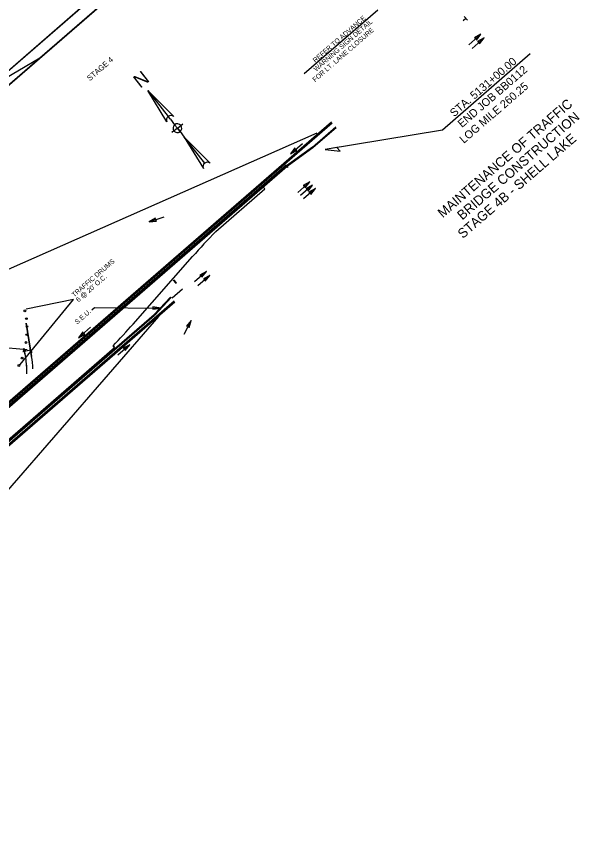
# Model space of a CAD drawing. Extents: x 259983 to 267998, y 211467 to 219827.
# Drawn here: x 266591 to 267998, y 211577 to 213621 of the extents above; entities that cross this region are included whole.
import ezdxf

# ---------------------------------------------------------------- set-up
doc = ezdxf.new("R2010")
doc.units = 0
for name, color, linetype in [('1', 7, 'Continuous'), ('Default', 7, 'Continuous'), ('DRAINAGE', 7, 'Continuous'), ('Level 1', 7, 'Continuous'), ('Level 24', 7, 'Continuous'), ('Level 43', 7, 'Continuous'), ('Level 58', 7, 'Continuous'), ('Level 59', 7, 'Continuous'), ('Level 6', 7, 'Continuous'), ('R_MOT', 7, 'Continuous'), ('R_MOT STAGE 1', 7, 'Continuous'), ('R_MOT STAGE 2', 7, 'Continuous')]:
    doc.layers.add(name, color=color, linetype=linetype)

msp = doc.modelspace()

# ---------------------------------------------------------------- linework, layer by layer
at = {"layer": '1'}
for p, q in [((266779.5, 212887.4), (266786.2, 212893.2)), ((266786.2, 212893.2), (266951.8, 212892.1))]:
    msp.add_line(p, q, dxfattribs=at)
for points in [[(265439.2, 211680.6), (266025.4, 212744.6), (266011.1, 212775.1), (266035.2, 212752.4), (267342.6, 213329.5)], [(265871.3, 211879.9), (266434.6, 212283), (266462.7, 212264.5), (266443.7, 212291.7), (266947.2, 212871.1)]]:
    msp.add_lwpolyline(points, dxfattribs=at)
msp.add_lwpolyline([(266931.9, 212889.3), (266951.8, 212892.1), (266932, 212895.3)], close=True, dxfattribs=at)
at = {"layer": 'Default'}
for p, q in [((266493.8, 213418.3), (267204.5, 214033.5)), ((266947.4, 213811), (266236.7, 213195.7)), ((266511.6, 213397.7), (266965.2, 213790.4)), ((266524.9, 213443.6), (266649.8, 213517.3))]:
    msp.add_line(p, q, dxfattribs=at)
at = {"layer": 'DRAINAGE'}
for p, q in [((266989.8, 212954.2), (266983.2, 212961.7)), ((266990.9, 212955.1), (266984.3, 212962.7)), ((266989.8, 212954.2), (266990.9, 212955.1))]:
    msp.add_line(p, q, dxfattribs=at)
at = {"layer": 'Level 1'}
for p, q in [((266919.6, 213435.8), (266984.5, 213370.5)), ((266967.3, 213357.1), (266919.6, 213435.8)), ((266919.6, 213435.8), (266970.6, 213370.6)), ((266975.9, 213363.8), (266970.6, 213370.6)), ((266975.9, 213363.8), (266986.7, 213350.1)), ((266986.7, 213350.1), (266993.4, 213341.5)), ((266993.4, 213341.5), (267001.9, 213348.2)), ((267001.9, 213348.2), (267007.1, 213352.2)), ((267001.9, 213348.2), (267001.9, 213348.2)), ((266984.5, 213334.5), (266979.6, 213330.8)), ((266993.4, 213341.5), (266985.1, 213335)), ((266993.4, 213341.5), (267000.1, 213332.9)), ((267000.1, 213332.9), (266993.4, 213341.5)), ((267000.1, 213332.9), (267010.8, 213319.2)), ((267010.8, 213319.2), (267058.5, 213240.4)), ((267061.7, 213254), (267010.8, 213319.2)), ((267010.8, 213319.2), (267075.7, 213253.8))]:
    msp.add_line(p, q, dxfattribs=at)
for centre, radius, start, end in [((266977.4, 213361.9), 11.2, 128, 205.3196), ((266977.4, 213361.9), 11.2, 50.6804, 128), ((266993.4, 213341.5), 10.9, 128, 218), ((266993.4, 213341.5), 10.9, 38, 128), ((266993.4, 213341.5), 10.9, 308, 38), ((266993.4, 213341.5), 10.9, 218, 308), ((267068.6, 213245.2), 11.2, 128, 205.3196), ((267068.6, 213245.2), 11.2, 50.6804, 128)]:
    msp.add_arc(centre, radius, start, end, dxfattribs=at)
at = {"layer": 'Level 24'}
for points in [[(267875.2, 213526.9), (267655.6, 213336.8)], [(267655.6, 213336.8), (267363, 213288.5)]]:
    msp.add_lwpolyline(points, dxfattribs=at)
at = {"layer": 'Level 43'}
for points in [[(267751.7, 213576), (267721.7, 213550)], [(267759.6, 213566.8), (267729.6, 213540.9)], [(267275.7, 213277.4), (267305.8, 213303.4)], [(267324.2, 213207.1), (267294.2, 213181.1)], [(267331.3, 213199), (267301.3, 213173)], [(267338.4, 213190.8), (267308.3, 213164.8)], [(266922.6, 213107.4), (266960.3, 213120)], [(267065.9, 212983.5), (267035.9, 212957.6)], [(267074.5, 212973.6), (267044.5, 212947.6)], [(267027.9, 212861.4), (267009.6, 212826.2)], [(266746.1, 212818.1), (266776.1, 212844.1)], [(266874.5, 212800.5), (266844.4, 212774.5)]]:
    msp.add_lwpolyline(points, dxfattribs=at)
at = {"layer": 'Level 58'}
for points in [[(267740.5, 213561.4), (267751.7, 213576), (267735.6, 213567.1), (267740.3, 213566.2)], [(267748.5, 213552.2), (267759.6, 213566.8), (267743.6, 213557.9), (267748.3, 213557)], [(267286.9, 213292.1), (267275.7, 213277.4), (267291.8, 213286.4), (267287.1, 213287.3)], [(267313, 213192.5), (267324.2, 213207.1), (267308.1, 213198.2), (267312.9, 213197.3)], [(267320.1, 213184.3), (267331.3, 213199), (267315.2, 213190), (267319.9, 213189.1)], [(267327.2, 213176.2), (267338.4, 213190.8), (267322.3, 213181.8), (267327, 213181)], [(266938.5, 213116.7), (266922.6, 213107.4), (266940.9, 213109.5), (266936.8, 213112.1)], [(267054.8, 212968.9), (267065.9, 212983.5), (267049.9, 212974.6), (267054.6, 212973.7)], [(267063.3, 212959), (267074.5, 212973.6), (267058.5, 212964.7), (267063.2, 212963.8)], [(267022.9, 212843.7), (267027.9, 212861.4), (267016.3, 212847.2), (267021, 212848.1)], [(266757.2, 212832.8), (266746.1, 212818.1), (266762.1, 212827.1), (266757.4, 212828)], [(266863.3, 212785.8), (266874.5, 212800.5), (266858.4, 212791.5), (266863.1, 212790.6)]]:
    msp.add_lwpolyline(points, close=True, dxfattribs=at)
at = {"layer": 'Level 59'}
msp.add_lwpolyline([(267392, 213293.3), (267363, 213288.5), (267400.5, 213284)], close=True, dxfattribs=at)
at = {"layer": 'R_MOT'}
for p, q in [((267714.1, 213615.6), (267707.6, 213610)), ((267710.1, 213620.2), (267718.1, 213611)), ((266607.2, 212783.5), (266631.1, 212788.2)), ((266610.3, 212784.1), (266611.7, 212776.8)), ((266627.9, 212787.6), (266629.3, 212780.3))]:
    msp.add_line(p, q, dxfattribs=at)
at = {"layer": 'R_MOT STAGE 1'}
for p, q in [((265394.8, 211640.2), (267378.2, 213357.2)), ((265396.8, 211637.9), (267380.1, 213354.9)), ((267330.8, 213294.4), (267389, 213344.7)), ((267332.1, 213292.8), (267390.3, 213343.2)), ((267330.8, 213294.4), (267266.4, 213247.2)), ((267332, 213292.7), (267267.5, 213245.5)), ((267265, 213248.7), (265792.3, 211973.7)), ((267266.4, 213247.2), (265793.6, 211972.2)), ((267267.7, 213245.6), (265967.2, 212119.8)), ((267265.6, 213248.1), (267269.7, 213243.3)), ((267208.2, 213194.1), (266893.5, 212921.7)), ((267089.2, 213083.2), (267212.1, 213189.6)), ((267212.1, 213189.6), (267208.2, 213194.1)), ((266882.8, 212852.2), (267031.5, 213020.7)), ((266980.1, 212917.3), (267006.4, 212940.1)), ((266887.5, 212916.5), (266683.1, 212739.6)), ((266893.5, 212921.7), (266887.5, 212916.5)), ((266976.6, 212919.6), (266935.4, 212876)), ((266978.1, 212918.2), (266936.9, 212874.6)), ((266976.6, 212919.6), (266978.1, 212918.2)), ((265447.8, 211578.9), (266985.1, 212909.8)), ((265449.8, 211576.7), (266987.1, 212907.5)), ((265889, 211970.1), (266935.4, 212876)), ((266935.4, 212876), (266936.9, 212874.6)), ((266936.7, 212874.5), (266935.4, 212876)), ((265890.3, 211968.6), (266936.7, 212874.5)), ((266615.3, 212854.1), (266629.4, 212770.9)), ((266629.4, 212770.9), (266615.3, 212854.1)), ((266832.8, 212797.7), (266836.7, 212793.2)), ((266836.7, 212793.2), (266832.8, 212797.7)), ((266227.9, 212266.2), (266836.7, 212793.2)), ((266614.6, 212768.4), (266610.6, 212792.1)), ((266683, 212739.5), (266652.2, 212712.8)), ((266652.2, 212712.8), (266629.8, 212693.5)), ((266629.8, 212693.5), (266586.5, 212656))]:
    msp.add_line(p, q, dxfattribs=at)
for centre in [(266612.7, 212885.3), (266616.2, 212865.6), (266617.8, 212845.7), (266617.5, 212825.7), (266615.3, 212805.9), (266611.3, 212786.3), (266605.4, 212767.2), (266597.6, 212748.7)]:
    msp.add_circle(centre, 2.25, dxfattribs=at)
for centre, radius, start, end in [((268451.3, 211767.4), 1893.9, 135.9906, 138.5667), ((265438.9, 214126.7), 1925.9, 316.3658, 318.5667), ((266424.8, 212736.3), 192.5, 357.5708, 9.5976), ((266424.8, 212736.3), 192.5, 357.3485, 9.5976), ((266424.8, 212736.3), 207.5, 1.1658, 9.5976), ((266682.7, 212740), 0.557, 301.5099, 309.0099)]:
    msp.add_arc(centre, radius, start, end, dxfattribs=at)
at = {"layer": 'R_MOT STAGE 2'}
for p, q in [((267494.3, 213636.6), (267309.9, 213476.9)), ((266600.8, 212751.4), (266734.1, 212913.4)), ((266734.1, 212913.4), (266616.1, 212889.2)), ((266508.1, 212798.2), (266617.8, 212788.2))]:
    msp.add_line(p, q, dxfattribs=at)
msp.add_lwpolyline([(266493.8, 213418.3), (266511.6, 213397.7), (266965.2, 213790.4), (266947.4, 213811)], close=True, dxfattribs=at)

# ---------------------------------------------------------------- texts
at = {"layer": '1'}
for s, height, rotation, p in [('REFER TO ADVANCE', 12, 40.8921, (267338, 213504.4)), ('WARNING SIGN DETAIL', 12, 40.8921, (267340.1, 213482.4)), ('FOR LT. LANE CLOSURE', 12, 40.8921, (267337.3, 213456.1)), ('STAGE 4', 14, 40.8733, (266774.9, 213458.6)), ('S.E.U.', 12, 40.8933, (266742.9, 212850.3))]:
    msp.add_text(s, height=height, rotation=rotation, dxfattribs=at).set_placement(p)
at = {"layer": 'Level 1'}
msp.add_text('N', height=34.2, rotation=38, dxfattribs=at).set_placement((266900.4, 213439.9))
at = {"layer": 'Level 24'}
for s, height, rotation, p in [('STA. 5131+00.00', 20, 40.8833, (267684.9, 213368.4)), ('END JOB BB0112', 20, 40.8833, (267704.5, 213341.7)), ('LOG MILE 260.25', 20, 40.8833, (267709.2, 213302.1)), ('TRAFFIC DRUMS', 12, 40.8835, (266735.8, 212918.5)), ("6 @ 20' O.C.", 12, 40.8835, (266746.5, 212906.2))]:
    msp.add_text(s, height=height, rotation=rotation, dxfattribs=at).set_placement(p)
at = {"layer": 'Level 6'}
for s, p in [('MAINTENANCE OF TRAFFIC', (267656.5, 213116.2)), ('BRIDGE CONSTRUCTION', (267705.2, 213110.7)), ('STAGE 4B - SHELL LAKE', (267706.6, 213064.4))]:
    msp.add_text(s, height=24, rotation=40.8733, dxfattribs=at).set_placement(p)

doc.saveas('drawing.dxf')
